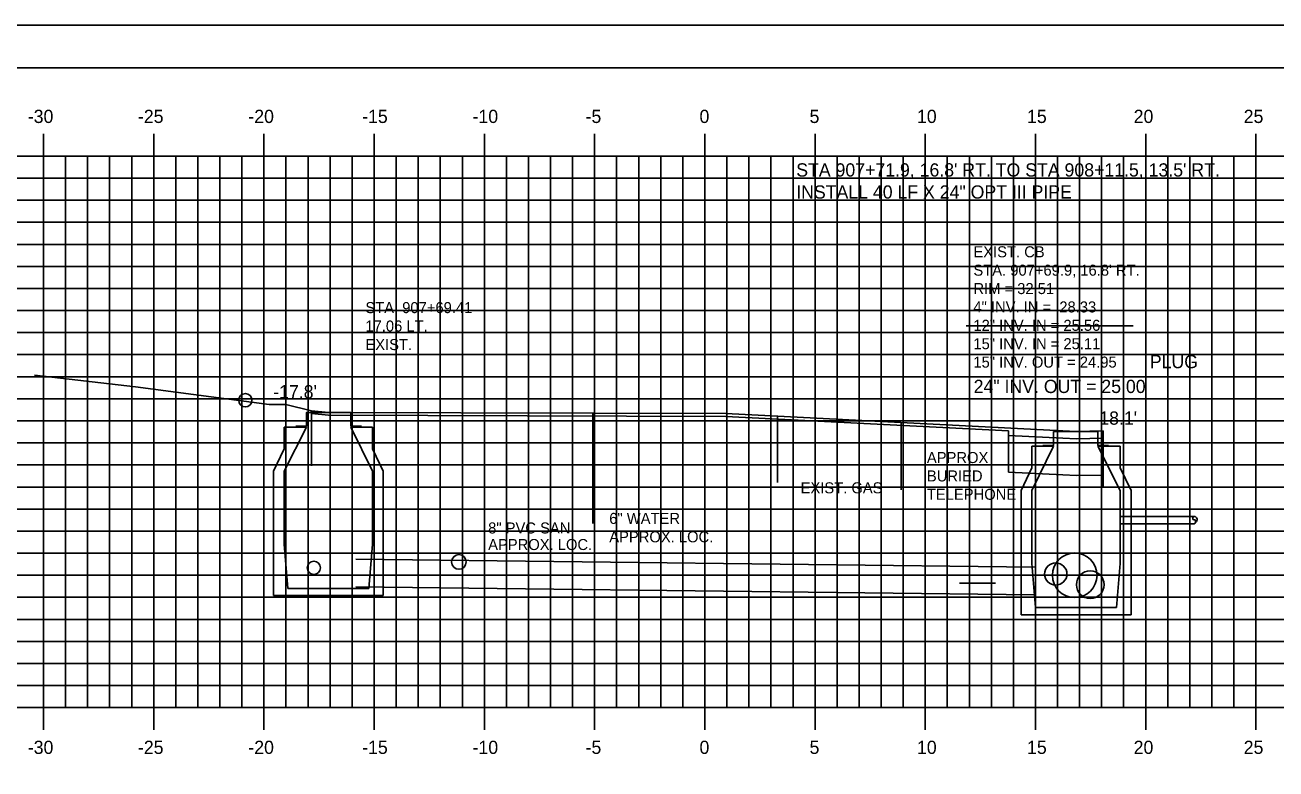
# Model space of a CAD drawing. Extents: x 1025909 to 1026079, y 394697 to 394807.
# Drawn here: x 1025960.8 to 1026017.6, y 394772.8 to 394806.5 of the extents above; entities that cross this region are included whole.
import ezdxf

# ---------------------------------------------------------------- set-up
doc = ezdxf.new("R2010")
doc.units = 0
for name, color, linetype in [('ANNOTATION', 7, 'Continuous'), ('BORDER', 7, 'Continuous'), ('D_Drainage_Culvert', 7, 'Continuous'), ('D_Drainage_Text', 7, 'Continuous'), ('D_Roadway_FinishedGrade', 7, 'Continuous'), ('D_Text_Monospaced', 7, 'Continuous'), ('D_Text_Standard', 7, 'Continuous'), ('H_V ANNOTATION', 7, 'Continuous'), ('MAJOR', 7, 'Continuous'), ('MINOR', 7, 'Continuous'), ('PLOT BOUNDARY', 7, 'Continuous'), ('S_Drainage_CB', 7, 'Continuous'), ('S_Drainage_Culvert_Top', 7, 'Continuous'), ('S_Drainage_Invert', 7, 'Continuous'), ('S_Roadway_Centerline', 7, 'Continuous'), ('S_Roadway_Edge_Pavement', 7, 'Continuous'), ('S_Utilities_UG_Gas_Line', 7, 'Continuous'), ('S_Utilities_UG_Sanitary_Sewer', 7, 'Continuous'), ('S_Utilities_UG_Water_Line', 7, 'Continuous')]:
    doc.layers.add(name, color=color, linetype=linetype)

msp = doc.modelspace()

# ---------------------------------------------------------------- linework, layer by layer
at = {"layer": 'ANNOTATION'}
msp.add_line((1026003.237, 394781.255), (1026004.856, 394781.255), dxfattribs=at)
at = {"layer": 'BORDER'}
msp.add_line((1026076.677, 394804.607), (1025916.677, 394804.607), dxfattribs=at)
at = {"layer": 'D_Drainage_Culvert'}
msp.add_line((1026003.54, 394792.92), (1026011.101, 394792.92), dxfattribs=at)
msp.add_circle((1026008.458, 394781.607), 1.012, dxfattribs=at)
at = {"layer": 'D_Roadway_FinishedGrade'}
for p, q in [((1025973.833, 394788.941), (1025973.833, 394789.066)), ((1026005.452, 394786.28), (1026005.452, 394788.155)), ((1026009.74, 394788.022), (1026009.74, 394788.147))]:
    msp.add_line(p, q, dxfattribs=at)
for points in [[(1025973.833, 394789.066), (1025974.613, 394788.991), (1025992.624, 394788.935), (1026007.925, 394788.154), (1026008.539, 394788.129), (1026009.74, 394788.147)], [(1025973.833, 394788.941), (1025974.613, 394788.866), (1025992.624, 394788.81), (1026005.452, 394788.155)], [(1026005.452, 394787.947), (1026007.925, 394787.821), (1026008.539, 394787.796), (1026009.74, 394787.814)], [(1026005.452, 394786.28), (1026007.925, 394786.154), (1026008.539, 394786.129), (1026009.74, 394786.147)]]:
    msp.add_lwpolyline(points, dxfattribs=at)
at = {"layer": 'MAJOR'}
for p, q in [((1025961.677, 394801.609), (1025961.677, 394800.607)), ((1025966.677, 394801.609), (1025966.677, 394800.607)), ((1025971.677, 394801.609), (1025971.677, 394800.607)), ((1025976.677, 394801.609), (1025976.677, 394800.607)), ((1025981.677, 394801.609), (1025981.677, 394800.607)), ((1025986.677, 394801.609), (1025986.677, 394800.607)), ((1025991.677, 394801.609), (1025991.677, 394800.607)), ((1025996.677, 394801.609), (1025996.677, 394800.607)), ((1026001.677, 394801.609), (1026001.677, 394800.607)), ((1026006.677, 394801.609), (1026006.677, 394800.607)), ((1026011.677, 394801.609), (1026011.677, 394800.607)), ((1026016.677, 394801.609), (1026016.677, 394800.607)), ((1025921.677, 394800.607), (1026061.677, 394800.607)), ((1025961.677, 394775.607), (1025961.677, 394800.607)), ((1025966.677, 394775.607), (1025966.677, 394800.607)), ((1025971.677, 394775.607), (1025971.677, 394800.607)), ((1025976.677, 394775.607), (1025976.677, 394800.607)), ((1025981.677, 394775.607), (1025981.677, 394800.607)), ((1025986.677, 394775.607), (1025986.677, 394800.607)), ((1025991.677, 394775.607), (1025991.677, 394800.607)), ((1025996.677, 394775.607), (1025996.677, 394800.607)), ((1026001.677, 394775.607), (1026001.677, 394800.607)), ((1026006.677, 394775.607), (1026006.677, 394800.607)), ((1026011.677, 394775.607), (1026011.677, 394800.607)), ((1026016.677, 394775.607), (1026016.677, 394800.607)), ((1025921.677, 394795.607), (1026061.677, 394795.607)), ((1025921.677, 394790.607), (1026061.677, 394790.607)), ((1025921.677, 394785.607), (1026061.677, 394785.607)), ((1025921.677, 394780.607), (1026061.677, 394780.607)), ((1025921.677, 394775.607), (1026061.677, 394775.607)), ((1025961.677, 394774.605), (1025961.677, 394775.607)), ((1025966.677, 394774.605), (1025966.677, 394775.607)), ((1025971.677, 394774.605), (1025971.677, 394775.607)), ((1025976.677, 394774.605), (1025976.677, 394775.607)), ((1025981.677, 394774.605), (1025981.677, 394775.607)), ((1025986.677, 394774.605), (1025986.677, 394775.607)), ((1025991.677, 394774.605), (1025991.677, 394775.607)), ((1025996.677, 394774.605), (1025996.677, 394775.607)), ((1026001.677, 394774.605), (1026001.677, 394775.607)), ((1026006.677, 394774.605), (1026006.677, 394775.607)), ((1026011.677, 394774.605), (1026011.677, 394775.607)), ((1026016.677, 394774.605), (1026016.677, 394775.607))]:
    msp.add_line(p, q, dxfattribs=at)
at = {"layer": 'MINOR'}
for p, q in [((1025962.677, 394775.607), (1025962.677, 394800.607)), ((1025963.677, 394775.607), (1025963.677, 394800.607)), ((1025964.677, 394775.607), (1025964.677, 394800.607)), ((1025965.677, 394775.607), (1025965.677, 394800.607)), ((1025967.677, 394775.607), (1025967.677, 394800.607)), ((1025968.677, 394775.607), (1025968.677, 394800.607)), ((1025969.677, 394775.607), (1025969.677, 394800.607)), ((1025970.677, 394775.607), (1025970.677, 394800.607)), ((1025972.677, 394775.607), (1025972.677, 394800.607)), ((1025973.677, 394775.607), (1025973.677, 394800.607)), ((1025974.677, 394775.607), (1025974.677, 394800.607)), ((1025975.677, 394775.607), (1025975.677, 394800.607)), ((1025977.677, 394775.607), (1025977.677, 394800.607)), ((1025978.677, 394775.607), (1025978.677, 394800.607)), ((1025979.677, 394775.607), (1025979.677, 394800.607)), ((1025980.677, 394775.607), (1025980.677, 394800.607)), ((1025982.677, 394775.607), (1025982.677, 394800.607)), ((1025983.677, 394775.607), (1025983.677, 394800.607)), ((1025984.677, 394775.607), (1025984.677, 394800.607)), ((1025985.677, 394775.607), (1025985.677, 394800.607)), ((1025987.677, 394775.607), (1025987.677, 394800.607)), ((1025988.677, 394775.607), (1025988.677, 394800.607)), ((1025989.677, 394775.607), (1025989.677, 394800.607)), ((1025990.677, 394775.607), (1025990.677, 394800.607)), ((1025992.677, 394775.607), (1025992.677, 394800.607)), ((1025993.677, 394775.607), (1025993.677, 394800.607)), ((1025994.677, 394775.607), (1025994.677, 394800.607)), ((1025995.677, 394775.607), (1025995.677, 394800.607)), ((1025997.677, 394775.607), (1025997.677, 394800.607)), ((1025998.677, 394775.607), (1025998.677, 394800.607)), ((1025999.677, 394775.607), (1025999.677, 394800.607)), ((1026000.677, 394775.607), (1026000.677, 394800.607)), ((1026002.677, 394775.607), (1026002.677, 394800.607)), ((1026003.677, 394775.607), (1026003.677, 394800.607)), ((1026004.677, 394775.607), (1026004.677, 394800.607)), ((1026005.677, 394775.607), (1026005.677, 394800.607)), ((1026007.677, 394775.607), (1026007.677, 394800.607)), ((1026008.677, 394775.607), (1026008.677, 394800.607)), ((1026009.677, 394775.607), (1026009.677, 394800.607)), ((1026010.677, 394775.607), (1026010.677, 394800.607)), ((1026012.677, 394775.607), (1026012.677, 394800.607)), ((1026013.677, 394775.607), (1026013.677, 394800.607)), ((1026014.677, 394775.607), (1026014.677, 394800.607)), ((1026015.677, 394775.607), (1026015.677, 394800.607)), ((1025921.677, 394799.607), (1026061.677, 394799.607)), ((1025921.677, 394798.607), (1026061.677, 394798.607)), ((1025921.677, 394797.607), (1026061.677, 394797.607)), ((1025921.677, 394796.607), (1026061.677, 394796.607)), ((1025921.677, 394794.607), (1026061.677, 394794.607)), ((1025921.677, 394793.607), (1026061.677, 394793.607)), ((1025921.677, 394792.607), (1026061.677, 394792.607)), ((1025921.677, 394791.607), (1026061.677, 394791.607)), ((1025921.677, 394789.607), (1026061.677, 394789.607)), ((1025921.677, 394788.607), (1026061.677, 394788.607)), ((1025921.677, 394787.607), (1026061.677, 394787.607)), ((1025921.677, 394786.607), (1026061.677, 394786.607)), ((1025921.677, 394784.607), (1026061.677, 394784.607)), ((1025921.677, 394783.607), (1026061.677, 394783.607)), ((1025921.677, 394782.607), (1026061.677, 394782.607)), ((1025921.677, 394781.607), (1026061.677, 394781.607)), ((1025921.677, 394779.607), (1026061.677, 394779.607)), ((1025921.677, 394778.607), (1026061.677, 394778.607)), ((1025921.677, 394777.607), (1026061.677, 394777.607)), ((1025921.677, 394776.607), (1026061.677, 394776.607))]:
    msp.add_line(p, q, dxfattribs=at)
at = {"layer": 'PLOT BOUNDARY'}
msp.add_lwpolyline([(1025908.583, 394696.548), (1026078.583, 394696.548), (1026078.583, 394806.548), (1025908.583, 394806.548)], close=True, dxfattribs=at)
at = {"layer": 'S_Drainage_CB'}
for p, q in [((1025972.595, 394787.342), (1025972.595, 394788.326)), ((1025972.595, 394788.326), (1025973.612, 394788.326)), ((1025973.612, 394788.326), (1025972.595, 394786.325)), ((1025975.613, 394788.326), (1025976.597, 394788.326)), ((1025976.597, 394786.325), (1025975.613, 394788.326)), ((1025976.597, 394788.326), (1025976.597, 394787.342)), ((1025972.103, 394786.325), (1025972.595, 394787.342)), ((1025976.597, 394787.342), (1025977.09, 394786.325)), ((1026007.501, 394787.454), (1026006.516, 394787.454)), ((1026006.516, 394787.454), (1026006.516, 394786.47)), ((1026006.516, 394785.452), (1026007.501, 394787.454)), ((1026010.519, 394787.454), (1026009.502, 394787.454)), ((1026009.502, 394787.454), (1026010.519, 394785.452)), ((1026010.519, 394786.47), (1026010.519, 394787.454)), ((1025972.103, 394780.682), (1025972.103, 394786.325)), ((1025972.595, 394786.325), (1025972.595, 394783.011)), ((1025976.597, 394783.011), (1025976.597, 394786.325)), ((1025977.09, 394786.325), (1025977.09, 394780.682)), ((1026006.516, 394786.47), (1026006.024, 394785.452)), ((1026011.011, 394785.452), (1026010.519, 394786.47)), ((1026006.024, 394785.452), (1026006.024, 394779.809)), ((1026006.516, 394782.139), (1026006.516, 394785.452)), ((1026010.519, 394785.452), (1026010.519, 394782.139)), ((1026011.011, 394779.809), (1026011.011, 394785.452)), ((1025972.595, 394783.011), (1025972.759, 394781.01)), ((1025976.433, 394781.01), (1025976.597, 394783.011)), ((1026006.68, 394780.138), (1026006.516, 394782.139)), ((1026010.519, 394782.139), (1026010.355, 394780.138)), ((1025977.09, 394780.682), (1025972.103, 394780.682)), ((1025972.759, 394781.01), (1025976.433, 394781.01)), ((1026010.355, 394780.138), (1026006.68, 394780.138)), ((1026006.024, 394779.809), (1026011.011, 394779.809))]:
    msp.add_line(p, q, dxfattribs=at)
for points in [[(1025973.12, 394788.368), (1025973.612, 394788.368), (1025973.612, 394788.991), (1025975.613, 394788.991), (1025975.613, 394788.368), (1025976.105, 394788.368)], [(1026009.994, 394787.495), (1026009.502, 394787.495), (1026009.502, 394788.119), (1026007.501, 394788.119), (1026007.501, 394787.495), (1026007.008, 394787.495)]]:
    msp.add_lwpolyline(points, dxfattribs=at)
at = {"layer": 'S_Drainage_Culvert_Top'}
for p, q in [((1026010.519, 394784.269), (1026013.869, 394784.269)), ((1026010.519, 394783.935), (1026013.869, 394783.935)), ((1026006.648, 394781.967), (1025975.852, 394782.334)), ((1026006.633, 394780.717), (1025975.838, 394781.084))]:
    msp.add_line(p, q, dxfattribs=at)
for centre, radius in [((1026007.595, 394781.663), 0.507), ((1026009.162, 394781.18), 0.625)]:
    msp.add_circle(centre, radius, dxfattribs=at)
for centre, radius, start, end in [((1026013.884, 394784.192), 0.0782, 101.4208, 292.9698), ((1026013.879, 394784.135), 0.134, 297.2663, 94.4215), ((1026013.829, 394784.043), 0.115, 290.2842, 41.7606)]:
    msp.add_arc(centre, radius, start, end, dxfattribs=at)
at = {"layer": 'S_Drainage_Invert'}
for centre in [(1025970.833, 394789.539), (1025973.941, 394781.946)]:
    msp.add_circle(centre, 0.3, dxfattribs=at)
at = {"layer": 'S_Roadway_Centerline'}
msp.add_lwpolyline([(1025961.275, 394790.674), (1025965.853, 394790.144), (1025971.909, 394789.345), (1025972.677, 394789.346), (1025973.833, 394789.066), (1025974.613, 394788.991), (1025992.624, 394788.935), (1026007.925, 394788.154), (1026008.539, 394788.129), (1026009.74, 394788.147)], dxfattribs=at)
at = {"layer": 'S_Roadway_Edge_Pavement'}
for p, q in [((1025973.833, 394789.066), (1025973.833, 394786.566)), ((1026009.74, 394788.147), (1026009.74, 394785.647))]:
    msp.add_line(p, q, dxfattribs=at)
at = {"layer": 'S_Utilities_UG_Gas_Line'}
msp.add_line((1025994.981, 394788.815), (1025994.981, 394785.815), dxfattribs=at)
at = {"layer": 'S_Utilities_UG_Sanitary_Sewer'}
msp.add_circle((1025980.519, 394782.21), 0.333, dxfattribs=at)
at = {"layer": 'S_Utilities_UG_Water_Line'}
for p, q in [((1025986.595, 394788.954), (1025986.595, 394783.954)), ((1026000.59, 394788.529), (1026000.59, 394785.475))]:
    msp.add_line(p, q, dxfattribs=at)

# ---------------------------------------------------------------- texts
at = {"layer": 'D_Drainage_Text'}
for s, p in [("STA 907+71.9, 16.8' RT. TO STA 908+11.5, 13.5' RT.", (1025995.824, 394799.68)), ('INSTALL 40 LF X 24" OPT III PIPE', (1025995.824, 394798.68)), ('PLUG', (1026011.864, 394790.992)), ('24" INV. OUT = 25.00', (1026003.873, 394789.867))]:
    msp.add_text(s, height=0.6, dxfattribs=at).set_placement(p)
at = {"layer": 'D_Text_Monospaced'}
for s, height, p in [('EXIST. CB', 0.5, (1026003.861, 394796.019)), ("STA. 907+69.9, 16.8' RT.", 0.49998, (1026003.861, 394795.186)), ('RIM = 32.51', 0.49998, (1026003.861, 394794.352)), ('STA. 907+69.41', 0.49998, (1025976.279, 394793.489)), ('4" INV. IN =  28.33', 0.49998, (1026003.861, 394793.519)), ('17.06 LT.', 0.5, (1025976.279, 394792.655)), ('12" INV. IN = 25.56', 0.49998, (1026003.861, 394792.686)), ('EXIST. ', 0.5, (1025976.279, 394791.815)), ('15" INV. IN = 25.11', 0.49998, (1026003.861, 394791.853)), ('15" INV. OUT = 24.95', 0.49998, (1026003.861, 394791.019)), ('APPROX', 0.5, (1026001.751, 394786.693)), ('BURIED ', 0.5, (1026001.751, 394785.86)), ('EXIST. GAS', 0.5, (1025996.022, 394785.32)), ('TELEPHONE', 0.5, (1026001.751, 394785.027)), ('8" PVC SAN.', 0.49998, (1025981.848, 394783.5)), ('6" WATER', 0.5, (1025987.342, 394783.934)), ('APPROX. LOC.', 0.49998, (1025987.342, 394783.1)), ('APPROX. LOC.', 0.49998, (1025981.848, 394782.75))]:
    msp.add_text(s, height=height, dxfattribs=at).set_placement(p)
at = {"layer": 'D_Text_Standard'}
for s, p in [("-17.8'", (1025972.098, 394789.624)), ("18.1'", (1026009.572, 394788.432))]:
    msp.add_text(s, height=0.6, dxfattribs=at).set_placement(p)
at = {"layer": 'H_V ANNOTATION'}
for s, p in [('-30', (1025960.965, 394802.107)), ('-25', (1025965.962, 394802.107)), ('-20', (1025970.97, 394802.107)), ('-15', (1025976.133, 394802.107)), ('-10', (1025981.141, 394802.107)), ('-5', (1025986.267, 394802.107)), ('0', (1025991.436, 394802.107)), ('5', (1025996.428, 394802.107)), ('10', (1026001.302, 394802.107)), ('15', (1026006.294, 394802.107)), ('20', (1026011.131, 394802.107)), ('25', (1026016.123, 394802.107)), ('-30', (1025960.965, 394773.507)), ('-25', (1025965.962, 394773.507)), ('-20', (1025970.97, 394773.507)), ('-15', (1025976.133, 394773.507)), ('-10', (1025981.141, 394773.507)), ('-5', (1025986.267, 394773.507)), ('0', (1025991.436, 394773.507)), ('5', (1025996.428, 394773.507)), ('10', (1026001.302, 394773.507)), ('15', (1026006.294, 394773.507)), ('20', (1026011.131, 394773.507)), ('25', (1026016.123, 394773.507))]:
    msp.add_text(s, height=0.6, dxfattribs=at).set_placement(p)
at = {"layer": 'S_Roadway_Centerline'}
for s, p in [('C', (1025992.619, 394788.935)), ('L', (1025992.624, 394788.928))]:
    msp.add_text(s, height=0.0146, dxfattribs=at).set_placement(p)

doc.saveas('drawing.dxf')
